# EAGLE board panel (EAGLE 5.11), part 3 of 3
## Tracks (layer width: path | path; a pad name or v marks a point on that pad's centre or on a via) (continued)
N$125 (continued)
  Bottom 0.813: U5A1.A 118.49,78.61 110.5,78.61 | 108.92,78.61 106.64,78.61 104.78,80.47 U4A1.K
N$126
  Top 0.813: U3A1.K U10.P$1 | U4A1.A U9.P$2
  Bottom 0.813: U4A1.A 105.69,83.01 106.38,83.69 106.38,91.37 U3A1.K
N$127
  Top 0.813: U10.P$2 U3A1.A | U2A1.K U7.P$1
  Bottom 0.61: 113.6,94.4 | 113.6,94.4 115.27,94.4
  Bottom 0.813: U3A1.A 107.73,95.67 109.08,94.4 113.6,94.4 | 115.27,94.4 116.14,94.4 117.49,93.06 117.49,91.79 U2A1.K
N$128  (via drill 0.6)
  Top 0.813: R_U1.1 117.47,61.8 v116.7,62.58
  Bottom 0.406: Q4.3 117.17,61.32
  Bottom 0.813: 117.17,61.32 117.17,62.1 v116.7,62.58
N$129
  Top 0.254: 81.8,18.5 L4.1 | 81.8,18.5 84.81,18.5 84.81,21.45 IC12.7 | 81.8,18.5 C38.2
N$130
  Top 0.254: 83.6,21.95 L4.3 | 83.6,21.95 IC12.6 | C39.2 83.26,22.29 83.6,21.95
N$131
  Top 0.254: R30.1 85.53,23.43 | JP4.1 81.78,32.38 82.31,32.45 82.31,30 83.81,28.5 83.81,24.6 84.66,23.75 R30.1 | IC12.3 85.61,23.45 R30.1
  Top 0.406: RST.2 82.31,32.65 82.31,32.45
N$132
  Top 0.254: JP3.1 105.11,13.76 105.11,18.8 102.41,21.5 98.11,21.5 97.81,21.8 97.81,22.1 97.46,22.45 IC12.32
N$133
  Top 0.254: JP3.2 101.61,13.49 101.61,14.8 100.91,15.5 100.91,18.6 98.58,20.93 98.46,20.95 IC12.29
N$134
  Top 0.254: JP3.3 99.81,12.75 99.81,18.6 97.96,20.45 IC12.28
N$135
  Top 0.254: JP3.4 98.11,13.78 98.11,14.4 99.11,15.4 99.11,18.1 97.26,19.95 IC12.27
N$136
  Top 0.254: JP3.5 94.04,13.44 94.06,13.46 IC12.23
N$137
  Top 0.254: JP3.6 92.61,13.47 92.61,15.2 93.56,16.15 IC12.22
N$138
  Top 0.254: JP3.9 85.11,13.48 85.11,14.9 86.21,16 89.11,16 89.56,16.45 IC12.14
N$139
  Top 0.254: JP3.10 82.61,13.52 82.61,14.8 83.41,15.6 84.01,15.6 85.31,16.9 87.81,16.9 88.21,17.3 88.21,18.1 89.11,19 89.11,19.6 88.76,19.95 IC12.10
N$140
  Top 0.406: IC11.4 103.46,32.9 103.26,32.9 C44.2
N$141
  Top 0.254: R31.2 95.91,29.75 LED1.A
N$142
  Top 0.254: 96.09,26.13 LED1.C 95.91,24.45 IC12.36
N$143  (via drill 0.4)
  Top 0.254: v90.61,23.9 89.64,22.93 89.04,22.93 89.02,22.95 IC12.4 | 96.86,16.3 96.71,16.45 95.86,16.45 95.51,16.8 v95.51,18
  Top 0.406: BL/SW2.2 96.86,16.6 96.86,16.3
  Bottom 0.254: v90.61,23.9 90.71,23.9 92.01,22.6 92.01,20.7 94.81,18 v95.51,18
N$144
  Top 0.254: 98.16,26 97.91,25.35 97.91,24.3 97.56,23.95 IC12.35
  Top 0.406: 98.16,26 98.26,26 SW2.1
N$145
  Top 0.254: R32.1 101.26,22.8 LED2.A
N$146
  Top 0.254: 98.93,22.93 LED2.C 98.91,22.95 IC12.33
N$147
  Bottom 0.254: U$1.D+ 96.26,22.2 R34.2
N$148
  Bottom 0.254: U$1.D- 97.06,23 R33.2
N$149  (via drill 0.4)
  Top 0.254: IC12.19 92.06,19.05 92.71,19.7 92.71,21 93.51,21.8 93.51,22.4 v94.31,23.2
  Bottom 0.254: v94.31,23.2 95.16,23.2 R33.1
N$150  (via drill 0.4)
  Top 0.254: IC12.20 92.56,18.55 93.41,19.4 93.41,20.6 v94.61,21.8
  Bottom 0.254: R34.1 95.56,20.85 v94.61,21.8
N$151
  Top 0.254: IC12.46 90.06,27.45 89.61,27.9 R35.1
N$152
  Top 0.254: IC12.47 89.56,27.05 88.31,28.3 R36.1
N$153
  Top 0.813: T3.8 4.71,107.6 4.01,108.3 4.01,113.75 R52.1
N$154
  Top 0.813: T3.5 8.82,111.41 10.21,112.8 14.36,112.8 R53.1
N$155
  Top 0.813: T4.8 32.2,114.06 R54.1
N$156
  Top 0.813: R53.2 19.66,115.35 18.61,116.4 17.8,116.4 G11.MP
N$157
  Top 0.813: R54.2 25.28,114.4 B11.MP
N$158
  Top 0.813: R55.2 26.57,117.8 W11.MP
N$159
  Top 0.813: T4.5 33.75,107.54 34.41,108.2 34.41,117.35 R55.1
N$160
  Top 0.305: IC16.10 33.11,91.4 R50.2
N$161
  Top 0.305: R51.1 C50.2
N$162
  Top 0.305: IC16.9 35.01,89.8 R51.2
N$163
  Top 0.254: L5.P$2 L1A1.P$2
  Top 0.305: IC16.3 26.01,89.3 C52.1
  Top 0.61: D10.K 23.76,90.3
  Top 1.016: 23.76,90.3 C52.1
  Top 1.422: D10.K 23.76,94.32 L5.P$2
N$164
  Top 0.3: R43.1 R44.2
  Top 0.305: IC16.8 35.11,89.3 R43.1
N$165
  Top 0.305: IC16.2 26.91,89.8 C52.2
N$166  (via drill 0.4)
  Top 0.254: IC16.5 29.22,88.3 v30.21,87.3 | IC15.12 17.61,96.81 18.56,95.85 R57.2
  Top 0.3: R57.2 v19.81,95.2
  Bottom 0.254: v30.21,87.3 22.31,95.2 v19.81,95.2
N$167
  Top 0.813: R52.2 R56.1
N$168
  Top 0.813: R56.2 10.16,114.35 11.52,115.71 R37.MP
N$169
  Top 0.35: IC14.16 104.39,46.78 104.11,46.5 104.11,45.5 104.41,45.2 109.01,45.2 109.22,45.01 X12.D-
N$170
  Top 0.35: X12.D+ 109.67,45.81 109.34,46.13 IC14.15
N$171
  Top 0.35: R45.1 114.79,52.56 RX2.A
N$172
  Top 0.35: R46.1 114.8,54.34 TX2.A
N$173
  Top 0.35: C55.1 109.45,47.94 108.94,47.43 IC14.17
N$174
  Top 0.35: RX2.C 109.97,52.56 108.29,50.68 IC14.22
N$175
  Top 0.35: IC14.23 107.64,51.33 108.11,51.8 108.11,53.9 108.55,54.34 TX2.C
N$176
  Top 0.35: C53.1 107.15,43.24 L6.1
  Top 0.406: X12.VBUS 109.32,44.21 109.12,44.01 C53.1 | L6.1 107.18,43.27
N$177
  Top 0.35: 109.61,53.2 109.61,53.6 109.11,53.4 109.61,53.2
N$178
  Top 0.35: IC14.14 97.19,46.13 R47.2 96.51,46.5
N$179  (via drill 0.6)
  other vias: 86.41,47.45 87.41,47 82.51,55.2 83.31,41.1 85.51,55.2 84.01,55.2 84.61,41.1 83.31,42.4
  pour Bottom (isolate 0.406): 88.78,56.57 80.36,56.57 80.36,39.3 88.78,39.3
  pour Top (isolate 0.406): 88.78,56.67 80.36,56.67 80.36,39.4 88.78,39.4
N$180  (via drill 0.4)
  Top 0.305: 5V1.1 84.78,50.17 85.41,50.8 OK6.8 | C58.1 88.21,49.4 88.51,49.1 v88.51,48.3 | v85.51,42.3 86.34,43.13 OK7.3
  Top 0.35: OK6.8
  Top 0.406: C58.1 OK6.8
  Bottom 0.305: v88.51,48.3 88.51,45.3 v85.51,42.3
N$181
  Top 0.305: TXD1.1 84.82,52.71 85.45,53.34 OK6.6
N$182
  Top 0.305: OK6.3 93.8,53.2 R48.1
N$183
  Top 0.305: R49.2 OK7.2
N$184
  Top 0.305: RXD1.1 85.21,47.63 R49.1
N$185
  Bottom 0.5: 14.49,72.5 18.81,72.5
  Bottom 0.61: X11.7 29.18,78.64 31.91,75.9 31.91,72.2 30.51,70.8 30.51,70.1 29.11,68.7 21.01,68.7 19.51,70.2 19.51,71.8 18.81,72.5 | X13.7 14.49,72.5
N$186
  Bottom 0.61: X11.8 26.48,80.5 28.91,80.5 33.11,76.3 33.11,71.7 32.01,70.6 32.01,69.3 30.11,67.4 18.61,67.4 16.99,69.02 X13.8
N$187
  Top 0.406: X14.7 11.86,50.25 13.51,48.6 15.21,48.6 16.01,49.4 16.01,50.5 16.71,51.2 19.21,51.2 20.11,50.3 26.21,50.3 28.41,48.1 32.71,48.1 33.51,48.9 33.51,56.8 32.24,58.08 X15.7
N$188
  Top 0.406: X15.8 28.37,59.35 29.51,58.2 29.51,57.3 29.91,56.9 31.81,56.9 32.71,56 32.71,49.2 32.41,48.9 28.91,48.9 26.81,51 20.31,51 19.41,51.9 15.85,51.9 X14.8
N$189
  Top 0.406: X16.8 17.25,30 23.61,30 25.11,28.5 30.11,28.5 30.71,29.1 30.71,37.8 29.31,39.2 26.48,39.2 X17.8
N$190
  Bottom 0.406: X17.7 28.44,37.4 24.21,37.4 20.41,33.6 16.31,33.6 14.46,31.75 X16.7
N$191  (via drill 0.4)
  Top 0.305: 14.59,6.53 IC19.16
  Top 0.406: v14.91,6.7 14.59,6.53 | v32.31,7.3 33.61,8.6 X18.D-
  Bottom 0.406: v14.91,6.7 15.21,6.9 17.01,6.9 17.81,6 31.01,6 v32.31,7.3
N$192  (via drill 0.4)
  Top 0.305: 15.79,5.88 IC19.15
  Top 0.406: v33.41,5.9 34.41,6.9 X18.D+ | v15.91,6 arc-90 15.79,5.88
  Bottom 0.406: v15.91,6 16.61,5.3 32.81,5.3 v33.41,5.9
N$193
  Top 0.406: R58.2 RX1.A
N$194
  Top 0.406: R59.2 TX1.A
N$195
  Top 0.305: IC19.17 13.09,7.18 C68.1
N$196
  Top 0.305: IC19.22 13.14,10.43 13.96,11.25
  Top 0.406: RX1.C 13.96,11.25
N$197
  Top 0.305: IC19.23 12.79,11.08 12.91,11.2 12.91,13.2 13.61,13.9
  Top 0.406: TX1.C 13.61,13.9
N$198
  Top 0.406: X18.VBUS 32.81,12.3 30.91,10.4 28.21,10.4 27.71,9.9 L7.1 27.03,7.4 C66.1
N$199
  Top 0.305: 6.61,5.1 5.84,5.88 IC19.14
  Top 0.406: R60.2 17.71,5.1 6.61,5.1
N$200
  Top 0.406: OK5.2 25.75,24.67 24.61,25.8 R63.2
N$201
  Top 0.406: OK4.2 36.58,15.77 35.21,14.4 28.21,14.4 28.21,12.8 27.61,12.2 R61.2
N$202
  Top 0.406: OK8.2 30.48,15.67 30.31,15.5 27.66,15.5 26.91,14.75 R62.2
N$203  (via drill 0.4)
  Top 0.305: 7.24,6.53 IC19.13
  Top 0.406: OK8.3 31.75,15.37 v31.81,15.3 | v8.31,7.6 7.24,6.53
  Bottom 0.406: v31.81,15.3 29.81,15.3 22.11,7.6 v8.31,7.6
N$204
  Top 1.27: W+1.MP 124.91,82.42 C20.2 125.06,80.06 L11.1
N$205
  Top 0.305: IC22.1 138.48,77.18 138.09,76.79 136.66,76.79 arc67 Q12.3
  Top 1.27: Q12.3 133.49,76.32 131.11,78.69 L11.2
  Bottom 1.27: D15.C 132.18,81.13 L11.2
N$206
  Top 0.305: IC22.4 140.43,76.84 R68.2
N$207
  Top 0.305: IC22.8 138.48,83.77 R69.1
N$208
  Top 0.305: 136.9,78.86 Q12.1 136.9,78.7 137.69,79.49 139.78,79.49 IC22.6
N$209  (via drill 0.4)
  Top 0.254: 134.04,86.72 137.85,86.72
  Top 0.305: IC23.3 139.78,88.22 137.85,88.22 137.85,86.72 | 134.04,86.72 132.14,88.62 132.14,89.75 131.66,90.22 130.17,90.22 129.72,89.78 129.72,86.6 v128.17,85.05
  Top 1.27: B-1.MP 123.11,87.31 C22.1
  Bottom 0.305: v128.17,85.05 127.03,86.19 R70.2
  Bottom 1.27: R70.2 124.36,86.76 B-1.MP
N$210
  Top 1.27: C22.2 | B+1.MP 124.91,91.74 C22.2 | C22.2 125.53,88.89 125.54,88.9 L12.1
N$211
  Top 0.305: IC23.1 138.48,86.47 138.17,86.16 136.49,86.16 Q13.3
  Top 1.27: Q13.3 135.95,85.53 133.41,85.53 130.96,87.98 L12.2
  Bottom 1.27: D16.C 132.18,90.11 130.97,88.9 L12.2
N$212
  Top 0.305: IC23.4 140.43,86.05 R71.2
N$213
  Top 0.305: IC23.8 138.48,93.14 R72.1
N$214
  Top 0.305: IC23.6 139.78,88.86 137.53,88.86 136.9,88.22 Q13.1
N$215  (via drill 0.4)
  Top 0.254: 134.04,96.04 137.85,96.04
  Top 0.305: IC24.3 139.78,97.43 137.85,97.43 137.85,96.04 | 134.04,96.04 132.3,97.79 132.3,98.07 131.5,98.86 130.23,98.86 129.72,98.35 129.72,95.81 v127.69,93.78
  Top 1.27: C25.1 123.11,96.64 G-1.MP
  Bottom 0.305: v127.69,93.78 127.03,94.44 R73.2
  Bottom 1.27: R73.2 124.29,95.45 G-1.MP
N$216
  Top 1.27: G+1.MP 124.91,101.03 C25.2 126.17,97.58 126.18,97.59 L13.1
N$217
  Top 0.305: IC24.1 138.48,95.75 138.17,95.45 136.45,95.45 Q14.3
  Top 1.27: 135.95,94.89 Q14.3 133.54,94.94 131.11,97.36 L13.2
  Bottom 1.27: D17.C 132.18,98.64 131.13,97.59 L13.2
N$218
  Top 0.305: IC24.4 140.43,95.42 R74.2
N$219
  Top 0.305: IC24.8 138.48,102.35 R75.1
N$220
  Top 0.305: IC24.6 139.78,98.07 137.69,98.07 136.9,97.27 Q14.1
N$221  (via drill 0.4)
  Top 0.305: IC25.3 139.78,69.49 138.01,69.49 137.85,69.33 137.85,68.06 v137.38,67.59 | 124.31,68.1 U-.MP 122.77,66.56 122.77,61.87 125.31,59.49 v138.49,59.49
  Top 1.27: C75.1 123.11,68.7 U-.MP
  Bottom 0.305: v138.49,59.49 138.49,66.63 137.53,67.59 v137.38,67.59
  Bottom 1.27: R76.2 125.3,69.09 U-.MP
N$222
  Top 1.27: U+.MP 124.91,73.12 C75.2 125.39,71.38 L14.1
N$223
  Top 0.305: Q15.3 136.31,66.63 137.85,66.63 138.49,67.27 IC25.1
  Top 1.27: 135.95,66.95 Q15.3 133.99,67 133.09,67.9 133.09,69.4 L14.2
  Bottom 1.27: D18.C 132.34,72.6 L14.2
N$224
  Top 0.305: IC25.4 140.43,67.48 R77.2
N$225
  Top 0.305: IC25.8 138.48,74.57 R78.1
N$226
  Top 0.305: 137.22,69.52 Q15.1 137.82,70.13 139.76,70.13 139.76,73.27 IC25.6
N$227
  Top 0.254: R80.2 135.76,50.15 135.18,49.57 IC26.29
N$228
  Top 0.254: 129.65,40.76 C78.2 | 129.65,40.76 IC26.8 | Q16.1 128.21,40.76 129.65,40.76
N$229
  Top 0.254: Q16.3 126.71,42.08 126.71,43.72 | IC26.7 128.94,41.56 128.94,43.72 126.71,43.72 | 126.71,43.72 C77.2
N$230
  Top 0.254: IC26.14 136.78,38.17 136.8,38.17 136.8,34.04 136.8,33.09 135.05,31.34 130.92,31.34 130.29,31.98 130.29,33.32 JP6.3
N$231
  Top 0.254: 135.42,35.31 R81.2 135.53,32.77 LED3.C
N$232
  Top 0.254: R81.1 135.98,37.06 IC26.13
N$233
  Top 0.254: JP5.3 134.1,49.99 134.33,49.76 134.38,49.64 IC26.30
N$234
  Bottom 0.406: C80.2 136.87,39.04 IC27.4
N$235  (via drill 0.4)
  Top 0.254: v138.38,35.71 137.58,35.71 IC26.15
  Bottom 0.254: S4.1 138.38,33.8 v138.38,35.71
  Bottom 0.406: S4.2 S4.1
N$236  (via drill 0.4)
  Top 0.305: v131.56,48.25 131.29,48.25 IC26.1
  Bottom 0.305: Q17.1 131.56,46.9 v131.56,48.25
N$237
  Bottom 0.406: Q17.3 126.95,45.95 JP5.2
N$238
  Top 0.254: LED4.C 133.78,34.67 R82.2
N$239
  Top 0.254: R82.1 133.58,37.55 IC26.10
N$240  (via drill 0.4)
  Top 0.3: v165.61,40.6 165.1,40.09 U$3.4
  Top 0.305: X3.2 168.65,39.63 166.68,37.67 U$2.4 165.7,36.81 165.61,36.9 v165.61,38.6
  Bottom 0.305: v165.61,40.6 v165.61,38.6
N$241  (via drill 0.4)
  Top 0.3: U$3.3 166.9,39.59
  Top 0.305: 170.41,40.43 X3.3 | 170.41,40.43 167.75,40.43 166.9,39.59 | U$2.2 170.03,34.81 v170.41,35.2 | 170.41,40.43 v170.41,41.4
  Bottom 0.305: v170.41,41.4 v170.41,35.2
N$242
  Top 0.3: U$3.9 161.57,47.07
  Top 0.305: 161.57,47.07 R83.2
N$243
  Top 0.254: R84.2 152.4,20.03 152.99,19.44 IC28.29
N$244
  Top 0.254: 161.79,13.91 C87.2 | 161.79,13.91 IC28.8 | Q18.1 161.79,12.47 161.79,13.91
N$245
  Top 0.254: Q18.3 160.47,10.98 158.83,10.98 | IC28.7 160.99,13.2 158.83,13.2 158.83,10.98 | C86.2 158.83,10.98
N$246
  Top 0.254: 167.25,19.68 R85.2 168.91,19.79 FRAME.C
N$247
  Top 0.254: R85.1 165.5,20.24 IC28.13
N$248
  Bottom 0.406: IC30.4 163.44,21.71 C89.2
N$249  (via drill 0.4)
  Top 0.254: v166.85,22.64 166.85,21.84 IC28.15
  Bottom 0.406: S1.2 S1.1 174.15,28.12 169.15,28.12 169.15,24.95 v166.85,22.64
N$250
  Top 0.254: BIND.C 167.88,18.04 R86.2
N$251
  Top 0.254: R86.1 165.01,17.84 IC28.10
N$252
  Bottom 0.406: IC29.4 172.8,22.63 C93.2
N$253
  Bottom 0.406: IC31.4 143.36,24.33 C96.2
N$254
  Top 0.406: IC28.30 152.68,18.64 151.53,19.79 151.53,24.23 153.04,25.74 165.74,25.74 167.96,23.52 167.96,22.17 169.07,21.06 169.15,21.06 173.84,16.37 SBUS.3
N$255
  Bottom 0.406: IC29.2 170.26,18.2 170.03,17.96 166.99,17.96 | 166.99,17.96 R87.1 | R88.2 | R88.2 166.99,17.96
N$256
  Top 0.305: IC32.20 137.58,15.28 C99.2
N$257
  Top 0.305: IC32.18 136.06,13.67 L15.2 C98.2
N$258
  Top 0.305: R93.2 131.95,24.89 132.16,25.1 134.31,25.1 134.46,24.95 134.46,24.09 LED5.A
N$259
  Top 0.305: LED6.A 136.44,24.78 136.71,25.05 139.7,25.05 R92.2
N$260
  Top 0.305: LED7.A 138.37,23.89 138.61,23.65 139.92,23.65 R91.2
N$261
  Top 0.305: LED8.A 132.69,23.38 R90.2
N$262  (via drill 0.4)
  Top 0.305: C102.1 139.66,16.45 139.66,18.26 SG4.+ | IC32.11 130.56,12.85 130.91,13.2 133.96,13.2 v134.46,13.7
  Bottom 0.305: SG4.+ 140.26,15.25 138.06,13.05 138.06,10.95 137.06,9.95 136.21,9.95 134.61,11.55 134.61,13.55 v134.46,13.7
N$263
  Top 0.305: IC32.24 136.05,19.09 137.41,20.45 137.96,20.45 138.31,20.8 138.31,21.7 LED7.C
N$264
  Top 0.305: IC32.25 135.78,19.97 136.36,20.55 136.36,21.71 LED6.C
N$265
  Top 0.305: IC32.26 133.76,20.65 133.96,20.85 133.96,20.9 134.31,21.25 134.31,21.44 LED5.C
N$266  (via drill 0.4)
  Top 0.305: IC32.23 137.44,17.68 v137.76,18
  Bottom 0.305: 137.85,18.09 R94.1 | 137.85,18.09 R95.1 | v137.76,18 137.85,18.09
N$267
  Top 0.305: IC32.27 132.95,19.98 LED8.C
N$268
  Top 0.406: R96.2 73.93,9.84 IC34.1
N$269
  Top 0.406: IC34.3 78.66,12.38 R97.2
N$270  (via drill 0.5)
  Top 0.406: v78.26,15.9 78.66,15.9 R97.1
  Bottom 0.406: LED-.1 77.61,15.9 v78.26,15.9
N$271  (via drill 0.5)
  Top 0.406: IC34.5 68.01,13.66 v68.01,14.15
  Bottom 0.406: v68.01,14.15 63.93,14.15 OUT.1
N$272  (via drill 0.5)
  Top 0.406: IC34.6 69.97,12.4 v68.01,12.4
  Bottom 0.406: v68.01,12.4 68.01,11.09 SW3.1
N$273  (via drill 0.5)
  Top 0.406: IC34.7 68.01,11.12 v68.01,9.15
  Bottom 0.406: v68.01,9.15 68.01,7.79 SW4.1
PB
  Top 0.406: IC1.26 165.64,91.9 R2.1 157.86,88.15 156.71,89.4 156.71,91.2 156.19,91.73 IC8.2
PB1
  Top 0.305: T4.2 26.64,110.15 R41.1 24.26,110.15 23.21,109.1 20.51,109.1 20.01,108.59 IC15.26
PG
  Top 0.406: IC1.27 166.41,91.09 163.31,88 163.31,74.5 162.95,74.14 R3.1 162.8,71.8 158.21,71.8 156.81,73.2 156.81,74.7 156.39,75.12 IC7.2
PG1
  Top 0.305: IC15.27 19.21,108.71 18.31,109.6 15.91,109.6 14.06,111.45 R40.1 11.69,111.45 T3.4
PR
  Top 0.406: IC6.2 156.49,60.33 158.61,58.2 161.31,58.2 161.71,57.8 162.31,57.8 162.66,57.45 R4.1 163.42,64.71 164.31,65.6 164.31,87.6 167.01,90.3 IC1.28
PR1
  Top 0.305: IC15.28 18.41,108.41 18.01,108.8 13.57,108.8 R39.1 13.35,108.87 T3.2
PW
  Top 0.406: IC3.2 155.79,107.62 156.51,106.9 156.51,104.9 157.21,104.2 163.01,104.2 | 163.01,104.2 163.01,96.4 166.72,92.7 IC1.25 | R5.1 163.01,105.84 163.01,104.2
PW1
  Top 0.305: T4.4 26.68,107.5 R42.1 24.31,107.5 23.81,108 21.44,108 IC15.25
RE/DE  (via drill 0.4)
  Top 0.305: D6.1 72.17,87.84 72.46,88.13 72.46,88.61 72.62,88.77 75,88.77 76.12,87.66 76.12,85.12 76.83,84.4 v77.94,84.4 | IC5.32 74.46,68.13 76.27,68.13 | 76.27,68.13 IC9.3 | 76.27,68.13 76.99,68.13 v77.31,68.45 77.31,66.92 IC9.2
  Bottom 0.305: v77.94,84.4 77.07,83.53 77.07,82.73 77.54,82.26 77.54,68.68 v77.31,68.45 | v77.94,84.4
RI_E
  Top 0.3: 151.38,39.09 U$3.17
  Top 0.305: SV1.10 151.38,39.09
RI_S  (via drill 0.4)
  Top 0.3: 163.32,36.09 U$3.1
  Top 0.305: v163.81,35.6 163.32,36.09
  Bottom 0.305: v163.81,35.6 160.71,35.6 158.61,37.7 147.11,37.7 146.01,36.5 146.01,34.55 X4.9
RS485A  (via drill 0.4, 0.6)
  Top 0.305: IC9.6 v76.27,58.84 76.04,58.6 73.42,58.6 73.42,57.81 72.68,57.81 SJ9.1
  Top 0.406: XL.3 68.42,36.3 68.5,36.22 68.5,35.43 68.97,34.95 68.97,33.2 69.29,32.89 77.7,32.89 78.34,32.25 v78.42,32.25 | 72.31,102.32 XR.3 72.23,105.36 72.78,105.91 78.26,105.91 v78.5,106.15 | v78.18,117.18 77.54,117.82 A_R.1 | v78.02,24 77.54,23.52 A_L.1
  Bottom 0.406: 78.81,106.23 78.81,60.19 78.5,59.87 76.75,59.87 76.27,59.4 v76.27,58.84 76.27,58.6 76.91,57.97 78.34,57.97 78.81,57.49 78.81,40.19 77.54,38.92 77.54,37.73 78.81,36.46 78.81,32.73 78.42,32.33 v78.42,32.25 78.73,31.93 78.81,31.93 78.81,24.95 78.02,24.16 v78.02,24 | v78.5,106.15 78.73,106.15 78.81,106.23 | 78.81,106.23 78.18,106.86 78.18,107.66 78.81,108.29 78.81,116.07 78.18,116.71 v78.18,117.18
RS485B  (via drill 0.4, 0.6)
  Top 0.305: IC9.7 v77.54,58.84 77.54,57.97 74.05,57.97 74.05,54.32 73.1,53.37 73.1,51.88 SJ8.1
  Top 0.406: XL.6 72.23,35.5 72.78,34.95 72.78,33.68 78.42,33.68 v78.42,38.28 | IC9.7 77.41,60.85 | XR.6 68.42,105.36 69.13,106.07 71.67,106.07 72.31,106.71 77.54,106.71 78.02,107.18 v79.29,107.18 | B_R.1 v79.29,117.18 | B_L.1 v79.29,24 | B_L.1
  Bottom 0.406: 79.61,58.84 79.61,107.18 | 79.61,110.2 | 79.61,58.84 v77.54,58.84 | 79.61,107.18 v79.29,107.18 | 79.61,107.18 79.61,110.2 | 79.61,110.2 79.61,116.87 v79.29,117.18 | v79.29,24 79.61,24.31 79.61,37.17 v78.42,38.28 79.61,39.47 79.61,58.84
RST  (via drill 0.4)
  Top 0.305: 69.29,52.1 JP3B.5 | R20.1 70.11,62.04 v70.56,62.49 72.15,64.08 72.15,66.38 71.12,67.41 IC5.29 | v69.61,49.71 70.64,48.68 72.54,48.68 73.18,48.13 73.18,44.71 75.32,42.57 75.72,42.57 75.72,41.7 v76.59,40.82 | 72.94,26.54 v75.48,26.54
  Top 0.406: 69.29,52.1 69.61,51.78 v69.61,49.71 | JP3A.5 72.94,26.54 | 72.94,26.54
  Bottom 0.305: v69.61,49.71 69.61,51.14 69.45,51.3 69.13,51.3 68.5,51.94 68.5,58.6 69.45,59.56 69.45,61.46 70.48,62.49 v70.56,62.49 | v76.59,40.82 76.59,40.27 76.04,39.71 76.04,27.09 v75.48,26.54
RST1  (via drill 0.4)
  Top 0.305: IC32.29 v131.36,21.65 130.29,21.65 R89.1
  Bottom 0.305: ISP2.5 133.16,11.08 133.16,20.5 132.01,21.65 v131.36,21.65
RTS_E
  Top 0.3: 158.61,44.8 160.57,42.84 U$3.11
  Top 0.305: SV1.4 153.29,44.8 158.61,44.8
RTS_S
  Top 0.3: 158.45,37.84 U$3.19
  Top 0.305: 158.45,37.84 158.01,37.4 149.41,37.4 148.51,36.5 148.51,34.51 X4.7
RX
  Top 0.254: JP4.5 91.94,33.73 89.61,31.4 R35.2
RX_E  (via drill 0.4)
  Top 0.3: 159.47,41.84 U$3.12
  Top 0.305: v157.81,43.5 159.47,41.84
  Bottom 0.305: v157.81,43.5 157.81,45.6 156.01,47.4 150.69,47.4 SV1.5
RX_S
  Top 0.3: 159.28,35.77 160.57,37.06 U$3.20
  Top 0.305: X4.2 159.28,35.77
RXD  (via drill 0.4)
  Top 0.406: v170.11,87.9 169.32,88.7 IC1.30 | IC2.1 169.55,81.24 169.81,81.5 169.81,82.9 v168.81,83.9
  Bottom 0.406: v168.81,83.9 168.81,86.6 v170.11,87.9
RXD2  (via drill 0.4)
  Top 0.305: IC15.30 16.81,105.51 v17.01,105.3 | v8.11,95.1 6.5,95.1 IC13.1
  Bottom 0.305: v17.01,105.3 17.01,102.9 v8.11,95.1
RXD3  (via drill 0.4)
  Top 0.305: v95.41,44.3 95.21,44.1 95.21,43.5 94.84,43.13 OK7.6
  Top 0.35: IC14.5 101.54,51.98 v101.81,51.7
  Top 0.406: OK7.6 93.49,43.2
  Bottom 0.35: 97.61,51.7 v101.81,51.7
  Bottom 0.406: 97.61,51.7 95.41,49.5 v95.41,44.3
RXD4
  Top 0.406: OK5.3 24.38,24.44 24.01,24.8 21.81,24.8 19.41,22.4 15.21,22.4 14.51,21.7 IC20.1
RXD_AL1  (via drill 0.4)
  Top 0.406: OK5.6 24.48,15.37 v24.41,15.3 | v9.61,11.3 6.61,11.3 6.19,11.73 IC19.5
  Bottom 0.406: v24.41,15.3 24.41,14.5 21.21,11.3 v9.61,11.3
SCK  (via drill 0.4)
  Top 0.305: IC1.17
  Top 0.406: IC1.17 175.35,95.24 v175.91,95.8
  Bottom 0.406: v175.91,95.8 175.91,96.29 ISP.3
SCK1  (via drill 0.4)
  Top 0.305: JP3B.3 66.75,51.3 v65.08,49.08 63.41,49.08 63.1,49.4 PB5.1 62.3,49.56 | v65.08,78.45 65.32,78.21 65.32,76.38 65.48,76.23 66.37,76.23 IC5.17 | JP3A.3 70.4,26.54 69.13,27.81 66.59,27.81 65.96,28.44 65.96,30.74 v64.92,31.78
  Bottom 0.305: v64.92,31.78 64.21,32.49 64.21,48.6 64.69,49.08 v65.08,49.08 65.05,49.52 65.05,50.54 64.21,51.38 64.21,59.4 65.48,60.67 65.48,70.51 64.84,71.15 64.84,76.62 65.32,77.1 65.32,78.21 v65.08,78.45
SCK2  (via drill 0.4)
  Top 0.305: v22.31,99.1 IC15.17
  Bottom 0.305: ISP1.3 25.63,102.42 v22.31,99.1
SCK3
  Top 0.305: ISP2.3 138.04,8.62 135.51,11.15 135.51,12.34 IC32.17
SCL
  Top 0.254: JP3.8 87.21,13.15 87.21,15 87.61,15.4 89.41,15.4 90.04,16.03 90.04,17.38 IC12.15
SDA
  Top 0.254: JP3.7 90.54,13.94 90.56,13.96 IC12.16
SPARE_B1  (via drill 0.4)
  Top 0.305: PB1.1 | PB1.1 62.46,34.47 62.86,34.08 v65.72,34.08 | JP2.3 67.96,44.38 v67.7,44.63 | IC5.13 70.24,77.58 70.24,76.54 69.84,76.15 v69.84,75.35 | v67.07,108.93 67.38,108.93 SW1.2
  Top 0.406: 71.67,45.75 71.67,44.46 JP2.3
  Bottom 0.305: v65.72,34.08 65.48,34.32 65.48,43.84 66.27,44.63 v67.7,44.63 68.65,45.51 68.65,45.9 68.65,49.4 68.65,50.98 67.86,51.78 67.86,58.76 68.65,59.56 68.65,62.1 69.13,62.57 69.13,67.81 70.08,68.76 70.08,73.69 69.92,73.84 69.92,75.27 v69.84,75.35 69.29,75.91 69.29,80.51 66.51,83.29 66.51,107.58 67.07,108.13 v67.07,108.93
SPARE_C3  (via drill 0.4)
  Top 0.305: PC3.1 62.15,46.92 JP2.6 63.98,47.97 v66.35,47.97 | IC5.26 68.72,68.35 v67.94,67.57 | SW1.3 68.45,108.05 66.43,108.05 v66.11,108.37
  Bottom 0.305: v66.35,47.97 66.59,48.13 66.59,50.67 65.96,51.3 65.96,59.24 66.75,60.03 66.75,65.75 67.94,66.94 v67.94,67.57 69.45,69.08 69.45,73.37 69.13,73.69 69.13,74.8 68.65,75.27 68.65,80.19 65.88,82.97 65.88,108.13 v66.11,108.37
SPARE_C4  (via drill 0.4)
  Top 0.305: 66.59,45.43 66.99,45.82 v67.7,45.82 | R21.1 67.46,62.18 v68.26,63.13 68.57,63.37 70.4,63.37 71.14,64.11 R28.1 | PC4.1 63.1,41.78 | PC4.1
  Top 0.406: JP2.5 66.43,44.46 | 66.59,45.43 66.59,44.46 JP2.5 | JP2.5 66.59,44.31 66.59,43.05 64.69,43.05 63.42,41.78 63.1,41.78 | 63.1,41.78
  Bottom 0.305: v67.7,45.82 68.02,46.14 68.02,48.13 68.02,49.56 68.02,50.83 67.23,51.62 67.23,58.92 68.02,59.72 68.02,62.89 v68.26,63.13
SPARE_C5  (via drill 0.4)
  Top 0.305: 69.06,46.86 v66.59,46.86 65.96,46.86 65.32,46.22 65.32,44.79 64.69,44.16 PC5.1 | R23.1 65.64,63.79 R29.1 66.17,64.85 67.07,65.75 v67.94,65.75 | PC5.1
  Top 0.406: 68.97,48.29 69.06,48.2 JP2.4 69.06,46.86
  Bottom 0.305: v66.59,46.86 67.23,47.49 67.23,50.83 66.59,51.46 66.59,59.08 67.38,59.87 67.38,65.19 v67.94,65.75
SPEC_RX
  Top 0.406: IC28.31 149.27,17.84 146.85,15.42 146.61,15.18 146.05,14.55 146.05,9.55 146.69,8.91 148.04,8.91 SPEKTRUM_TX.2
T_B  (via drill 0.4)
  Top 0.305: IC23.2 139.13,86.17 138.25,85.29 v137.3,85.29 | R19.1 JP1T2.4
  Bottom 0.305: JP1T2.4 132.14,64.73 135.47,68.06 135.47,84.73 136.03,85.29 v137.3,85.29
T_G  (via drill 0.4)
  Top 0.305: IC24.2 139.13,95.53 138.17,94.57 v137.22,94.57 | R22.1 JP1T2.3
  Bottom 0.305: v137.22,94.57 135.31,94.57 134.84,94.1 134.84,68.38 133.41,66.95 130.23,66.95 129.6,66.31 JP1T2.3
T_R  (via drill 0.4)
  Top 0.305: IC21.2 139.13,104.9 138.01,103.78 v137.22,103.78 | R24.1 JP1T2.2
  Bottom 0.305: v137.22,103.78 134.84,103.78 134.2,103.15 134.2,68.7 133.09,67.59 128.01,67.59 127.06,66.63 JP1T2.2
T_U
  Top 0.305: R79.1 JP1T2.6 137.22,65.05 139.12,66.95 139.12,67.43 139.13,67.43 IC25.2
T_W  (via drill 0.4)
  Top 0.305: IC22.2 139.13,76.96 138.09,75.92 v137.22,75.92 | R18.1 JP1T2.5
  Bottom 0.305: JP1T2.5 134.68,66.31 136.11,67.75 136.11,75.52 136.5,75.92 v137.22,75.92
TX
  Top 0.254: JP4.4 89.4,33.29 88.31,32.2 R36.2
TX_E
  Top 0.3: 155.51,44 158.42,41.09 U$3.13
  Top 0.305: SV1.3 150.71,47.42 150.71,45.3 152.01,44 155.51,44
TX_S
  Top 0.3: 159.31,34.5 161.07,36.26 U$3.21
  Top 0.305: X4.3 153.58,34.5 159.31,34.5
TXD
  Top 0.406: IC1.31 166.91,87.9 165.74,86.73 IC2.4
TXD2  (via drill 0.4)
  Top 0.305: IC5.31 72.72,68.03 73.58,67.18 74.51,67.18 IC9.4 75,65.59 75.8,64.8 v76.75,64.8 | D7.1 73.84,87.81 74.85,87.81 75.4,87.26 75.4,84.24 76.59,83.05 v77.94,83.05
  Bottom 0.305: 78.1,82.89 v77.94,83.05 78.18,82.81 78.18,66.22 v76.75,64.8
TXD3  (via drill 0.4)
  Top 0.305: IC15.31 16.01,105.59 v15.71,105.3 | v8.41,91.3 6.49,91.3 IC13.4
  Bottom 0.305: v15.71,105.3 15.71,102.8 8.11,96.3 7.61,96.3 6.71,95.4 6.71,93 v8.41,91.3
TXD4
  Top 0.305: R48.2 96.84,54.58 IC14.1
TXD5
  Top 0.406: OK4.6 37.85,21.74 37.21,21.1 20.41,21.1 20.11,20.8 18.91,20.8 18.32,20.21 IC20.4
TXD_AL1
  Top 0.406: OK4.3 37.85,18.47 36.91,18.6 22.41,18.6 21.31,17.5 21.31,16.4 20.41,15.5 10.21,15.5 9.04,14.33 IC19.1
V+
  Top 0.406: U1A.A U1.P$2
  Top 0.813: G1.A 87.29,112.11 83.73,112.11 83.41,112.11 82.45,113.06 81.85,113.06 R_R.2 81.69,113.06 82.3,113.06 | W1A.A W1.A@2
  Bottom 0.813: G1.A 91.07,108.33 B1.A 94.7,108.33 U1A.A 99.16,105.16 arc90 99.28,105.28 | JP1T.7 99.28,66.04 99.28,86.23 | 99.28,105.28 99.28,118.8 arc90 P+18T.1 | 99.28,86.23 99.28,105.28 | W1A.A 99.22,86.17 99.28,86.23
V+1
  Top 0.406: U1A1.A U6.P$2
  Top 0.813: G6.A 108.99,112.11 105.43,112.11 105.11,112.11 104.15,113.06 103.55,113.06 R_R1.2 103.39,113.06 104,113.06 | W1A1.A W7.A@2
  Bottom 0.813: G6.A 112.77,108.33 B6.A 116.4,108.33 U1A1.A 120.86,105.16 arc90 120.98,105.28 | JP1T1.7 120.98,66.04 120.98,86.23 | 120.98,105.28 120.98,118.8 arc90 P+18T1.1 | 120.98,86.23 120.98,105.28 | W1A1.A 120.92,86.17 120.98,86.23
VBUS  (via drill 0.4)
  Top 0.3: U$3.8 U$3.7 162.57,44.76
  Top 0.305: X3.1 171.25,38.83 169.23,36.81 U$2.3 168.58,37.87 v169.11,38.4 | 162.57,44.76 164.08,46.27 C84.2 166.01,46.17 v166.01,48.2
  Bottom 0.305: v169.11,38.4 169.11,45.1 v166.01,48.2
VCC  (via drill 0.4)
  Top 0.305: 62.15,59.4 PAD3.1 | 62.15,59.4
  Top 0.406: IC5.6 73.98,74.57 73.96,74.57 73.73,74.8 72.78,74.8 72.38,74.4 72.38,73.29 72.46,73.21 | R25.1 73.81,49.95 73.89,50.03 | 64.53,67.39 L3.1 | 78.81,61.62 79.61,62.41 79.61,68.45 77.6,70.46 C34.1 77.54,71.3 75.88,72.97 IC5.4 73.97,72.97 73.73,72.73 72.94,72.73 72.46,73.21 | 72.46,73.21
  Top 0.61: IC10.1 78.81,55.43 | IC10.1 78.81,54.16 78.81,52.89 74.37,52.89 73.89,52.89 73.89,50.03 73.89,48.29 | PAD4.1 62.15,59.4 | JP2.2 73.89,47.16 73.89,48.29 | C33.1 76.33,48.29 73.89,48.29 | IC10.1 IC9.8 78.81,61.62 78.81,61.78 78.34,62.26 73.89,62.26 73.1,61.46 70.72,61.46 69.5,60.24 R20.2 R21.2 R23.2 64.53,60.24 | 64.53,60.24 62.91,60.24 PAD3.1 | 64.53,60.24 v64.53,61.14 | v64.53,66.46 64.53,67.39
  Bottom 0.61: v64.53,61.14 v64.53,66.46
VCC1  (via drill 0.4)
  Top 0.3: U$3.5 U$3.6 164.1,41.09
  Top 0.305: C83.2 C82.2 165.15,42.44 165.01,42.3 | 165.01,42.3 164.61,41.9 164.61,41.6 164.1,41.09 | SV1.1 161.25,48.67 R83.1 163.28,49.03 163.81,48.5 v163.81,47.4 | v164.71,43.6 164.71,42.6 165.01,42.3
  Bottom 0.305: v163.81,47.4 163.81,44.5 v164.71,43.6
VCC2  (via drill 0.5)
  Top 0.406: 72.27,9.84 IC34.8 | 72.27,9.84 72.63,9.84 R96.1 63.84,7.36 VCC1.1 | 72.27,9.84 v72.27,12.65 72.25,12.65 C103.2
  Bottom 0.406: LED+.1 74.19,12.65 v72.27,12.65
XTAL1
  Top 0.406: 174.54,83.8 174.54,83.63 173.92,83.01 C5.2 | 174.54,83.8 IC1.7 | Q1.3 175.68,83.8 174.54,83.8
XTAL2
  Top 0.406: Q1.1 177.22,82.14 | IC1.8 178.11,85.6 178.11,82.3 177.88,82.07 Q1.1 | Q1.1 C4.2
XTAL3
  Top 0.406: Q6.3 10.78,100.75 | Q6.3 10.77,100.68 10.77,101.66 10.33,102.19 C45.2 | Q6.3 10.78,101.07 IC15.7
XTAL4
  Top 0.406: 9.38,97.74 12.67,97.74 13.71,98.78 IC15.8 | Q6.1 9.38,97.74 | 9.38,97.74 C46.2

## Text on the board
tPlace: C3 | C4 | C5 | B1 | +5V | GND | +18V | 6 | 1 | seb@exse.net | v3 | 4CH LED-Controller | seb@exse.net | Electron Buffer | 4CH LED-Controller | v2 | Power Injector | 1 | 7 | Spektrum | Data Injector | seb@exse.net | PPM | Bind
tNames: C3 | C4 | C5 | B1 | +5V | GND | +18V | C3 | C4 | C5 | B1 | +5V | GND | +18V | 1 | 1 | 6 | 6 | 8 | 4 | 2 | 1 | 32 | 16 | 1 | 7 | 1 | 7 | +5V | +5V | 1 | GND | GND | 26 | 33 | TX | RX | 15 | 14 | GND | 3V3 | 5V | +18 | 02 | 03 | SCL | SDA | 06 | 07 | 011
tStop: SpektrumTX | SBUS | seb@exse.net
bStop: https://github.com/alxlo/PentaFnord | R | G | rd | PowerLedBoard 0.1 | PentaFn | B | PentaFnord | PentaFnord | PentaFnord | LedBoard 0.9 | LedBoard 0.9 | W | U | CtrlBoard 0.9 | + | s | - | GND | - | s | + | LED- | OUT | 18 | LED+ | SW1 | s | s | 7.4 | 33 | - | 5 | 5 | SW2 | - | -
_tNames: +18 | R | G | B | W | L1 | D | R13 | C | A | B | 6 | 1 | JP2T | 6 | 1 | JP2T | JP2T | W+ | Q2 | R12 | C6 | R_R | R_R | R10 | R14 | R11 | R2 | T2 | SW1 | R11 | R3 | G1 | RD2 | G1 | RD2 | C1 | C7 | D2 | IC1 | R4 | R5 | R+ | C6 | IC3 | R8 | RD1 | B1 | RD1 | B1 | R5 | T1 | R- | C3 | L1 | R6 | C2 | B2 | U1 | B2 | U1 | Q1 | W- | R6 | C5 | R7 | Q1 | XR | RD3 | RD3 | R12 | R1 | W3 | W3 | C2 | B+ | L4 | G+ | IC2 | Q5 | R1 | IC1 | ISP | RD4 | RD4 | C7 | C14 | ISP | C4 | 7 | W2 | W2 | C8 | C23 | JP1 | G- | L2 | R7 | C3 | IC2 | C1 | U3 | G2 | U3 | G2 | D4 | R15 | L1 | C10 | D1 | 1 | Q2 | C15 | R8 | R13 | IC7 | G3 | U2 | G3 | U2 | R17 | D1 | IC3 | IC3 | IC4 | R9 | D5 | D6 | D7 | B+ | C8 | C3 | C11 | R7 | D2 | C3 | W4 | B3 | W4 | B3 | B- | C13 | B- | L3 | R8 | C12 | R6 | R15 | R2 | C26 | B4 | W1 | B4 | W1 | R16 | Q3 | IC1 | C7 | C6 | R14 | G+ | L3 | Q4 | C2 | Q1 | D3 | D4 | U4 | RD5 | U4 | RD5 | C4 | IC4 | C10 | PB0 | W+ | C9 | C4 | RD6 | RD6 | C5 | U5 | U5 | W- | L4 | R9 | ADC6 | D3 | C6 | IC1 | Q4 | C11 | IC6 | W5 | G4 | W5 | G4 | C12 | C7 | C4 | R14 | IC2 | R15 | C5 | G5 | RD7 | G5 | RD7 | C5 | U+ | IC5 | G- | C9 | ADC7 | C8 | L5 | R12 | R3 | IC4 | C27 | RD8 | B5 | RD8 | B5 | C10 | R10 | R13 | C1 | L1 | U- | C13 | PC0 | L2 | 7 | JP1T | 7 | JP1T | Q5 | R+ | Q3 | C8 | PC1 | R2 | JP1T | R3 | IC3 | +18 | 1 | 1 | PC2 | R5 | R4 | R1 | R_W | R_G | R_B | R_U | R_W | R_G | R_B | R_U | R1 | R2 | R3 | R4 | R5 | C9 | D1 | IC5 | PB2 | R7 | R11 | 6 | R6 | R- | C28 | TX | R9 | R10 | D2 | TXD | R2 | R4 | PB3 | IC4 | R5 | RX | 1 | R1 | 5V | PB4 | OK1 | JP3B | R8 | C1 | RXD | C8 | PB5 | 6 | C7 | OK2 | C4 | GND | JP2 | GND | PC3 | R3 | 1 | IC1 | L1 | C1 | C29 | PC5 | R6 | C2 | C2 | PC4 | C3 | GND | XL | GND | 26 | 33 | TX | RX | 15 | 14 | GND | 3V3 | 5V | PB1 | 6 | R2 | C6 | R7 | R6 | C5 | +18V | LED1 | JP3A | RST | C4 | IC2 | R24 | C7 | C30 | 1 | SW1 | C17 | C25 | IC1 | C22 | C | A | B | C15 | D | R1 | C1 | LED2 | C16 | +18 | R3 | IC8 | OK2 | C2 | IC6 | C3 | IC7 | OK3 | OK1 | BL/SW2 | TX | R17 | C24 | C1 | 02 | 03 | SCL | SDA | 06 | 07 | 011 | R22 | RX | R16 | GND | R19 | R2 | L2 | VCC | C21 | R1 | IC1 | C20 | C19 | C14 | R18
_bNames: +5V | U$1
_tValues: WIREPADSMD1,27-254 | WIREPADSMD1,27-254 | 33µH / 1A | SE14 | SE14 | RJ45-8L-B | 2.2µF / 50V | MOSFET-PCHANNEL | RJ45-8L-B | 1µF | MBRS140 | 47k | 100K | SE14 | 100K | 0R27 | LM3401 | 33µH / 1A | 5.6k | MEGA48/88/168-AU | 3,3µH | 8.2µH | SE14 | 2.2µF / 50V | 47µF 16V | MOSFET-PCHANNEL | 68k | 1µF | 68k | 680pF | MBRS140 | MBRS340 | 18k | 47k | 47k | 78L05SMD | SE14 | 33k | 1µF | 0R27 | LM3401 | 1µF | 100nF | LT3972 | 5.6k | MEGA48/88/168-AU | 150k | 33µH / 1A | 4.7µF 50V | 4.7µF 50V | RJ45-8L-B | SE14 | 2.2µF / 50V | MOSFET-PCHANNEL | WIREPADSMD1,27-254 | 22p | 1µF | 78L05SMD | MBRS140 | 47k | 100nF | 4.7µF 50V | SE14 | 100n | 1µF | 22p | WIREPADSMD1,27-254 | 0R27 | LM3401 | MEGA8-AI | 5.6k | RJ45-8L-B | 100n | 33µH / 1A | 10uH | 47R | MAX487 | SE14 | 47R | MOSFET-PCHANNEL | 2.2µF / 50V | SE14 | 10K | RJ45-8L-B | 680 | 1µF | 47k | RJ45-8L-B | MBRS140 | SE14 | 120 | FT232RL | LM3401 | 78L05 | 0R27 | 150R | 5.6k | 100nF | 150R | 100n | MOSFET-PCHANNEL | RJ45-8L-B | 680 | 100nF | SE14 | 100nF | 150R | 150R | BEAD | 1u | RJ45-8L-B | RJ45-8L-B | 4.7µF | 100nF | 10nF | 10µF | 10nF | 150R | 1µF | 100nF | 150R | 150R | LT1761 | 15k | 78L05 | MAX487 | 150R | WIREPADSMD1,27-254 | WIREPADSMD1,27-254 | 22pF | HCPL0601 | 100nF | 22pF | TINY13V-10SU | RJ45-8L-B | 4.7µF | FT232RL | USB-SMD-NS
_bValues: USB-MINIB-5PIN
